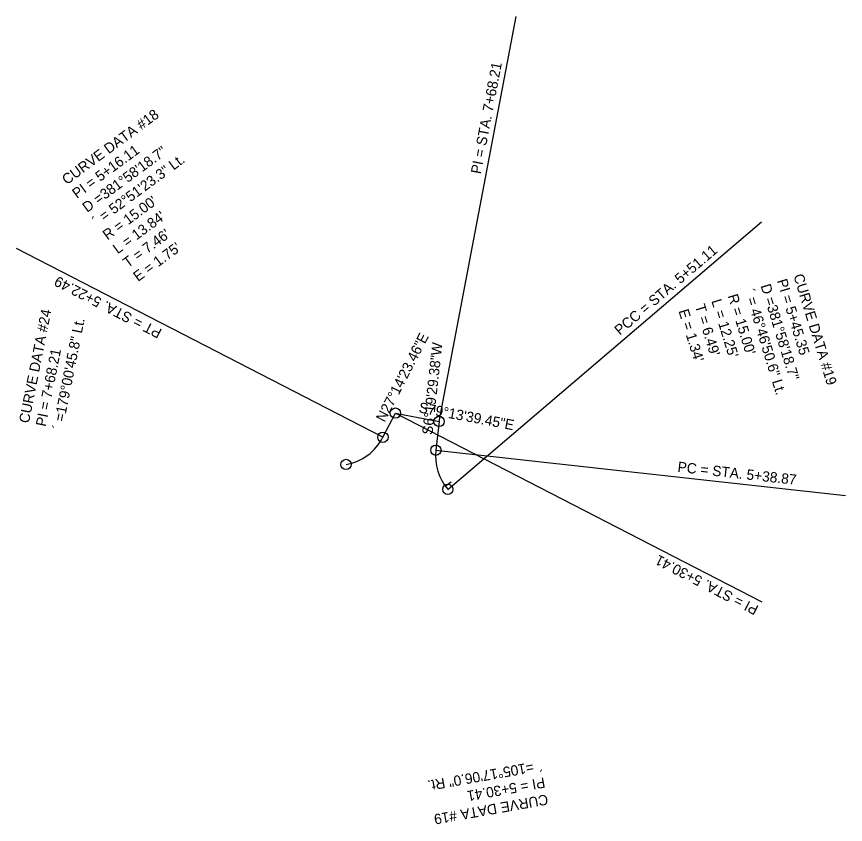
# Model space of a CAD drawing. Extents: x 1158784 to 1165006, y 610007 to 611539.
# Drawn here: x 1162069.8 to 1162311.2, y 610604.7 to 610839.9 of the extents above; entities that cross this region are included whole.
import ezdxf

# ---------------------------------------------------------------- set-up
doc = ezdxf.new("R2010")
doc.units = 0
for name, color, linetype in [('D_Roadway_Centerline', 7, 'Continuous'), ('D_Roadway_Centerline_Bearings', 7, 'Continuous'), ('D_Roadway_Centerline_CurveData', 7, 'Continuous'), ('D_Roadway_Centerline_Flags', 7, 'Continuous'), ('D_Roadway_Centerline_Text', 7, 'Continuous')]:
    doc.layers.add(name, color=color, linetype=linetype)

msp = doc.modelspace()

# ---------------------------------------------------------------- linework, layer by layer
at = {"layer": 'D_Roadway_Centerline'}
for p, q in [((1162176.52, 610717.41), (1162180.14, 610724.45)), ((1162180.14, 610724.45), (1162192.85, 610722.03)), ((1162192.85, 610722.05), (1162191.92, 610713.65))]:
    msp.add_line(p, q, dxfattribs=at)
for centre, start, end in [((1162163.18, 610724.28), 279.9037, 332.7602), ((1162206.83, 610712), 173.6752, 220.4559)]:
    msp.add_arc(centre, 15, start, end, dxfattribs=at)
at = {"layer": 'D_Roadway_Centerline_Flags'}
for points in [[(1162192.85, 610722.03), (1162215.28, 610839.92)], [(1162195.41, 610702.26), (1162286.72, 610780.13)], [(1162176.52, 610717.41), (1162069.83, 610772.34)], [(1162180.14, 610724.45), (1162286.83, 610669.52)], [(1162191.92, 610713.65), (1162311.19, 610700.43)]]:
    msp.add_lwpolyline(points, dxfattribs=at)
for centre in [(1162180.14, 610724.45), (1162180.14, 610724.45), (1162192.85, 610722.05), (1162192.85, 610722.03), (1162176.52, 610717.41), (1162191.92, 610713.65), (1162165.76, 610709.5), (1162195.41, 610702.26)]:
    msp.add_circle(centre, 1.5, dxfattribs=at)
at = {"layer": 'D_Roadway_Centerline_Text'}
msp.add_lwpolyline([(1162196.34, 610704.32), (1162194.72, 610703.14)], dxfattribs=at)

# ---------------------------------------------------------------- texts
at = {"layer": 'D_Roadway_Centerline_Bearings'}
for s, rotation, p in [('N27%%d14\'23.46"E', 62.7602, (1162176.99, 610721.62)), ('S6%%d19\'29.38"W', 83.6752, (1162190.89, 610718.02)), ('S79%%d13\'39.45"E', 349.2276, (1162186.77, 610724.71))]:
    msp.add_text(s, height=3, rotation=rotation, dxfattribs=at).set_placement(p)
at = {"layer": 'D_Roadway_Centerline_CurveData'}
for s, rotation, p in [('CURVE DATA #18', 36.3319, (1162084.45, 610790.82)), ('PI = 5+16.11', 36.3319, (1162087.41, 610786.79)), ('D =381%%d58\'18.7"', 36.3319, (1162090.38, 610782.76)), ('´ = 52%%d51\'23.3" Lt.', 36.3319, (1162093.34, 610778.74)), ("R = 15.00'", 36.3319, (1162096.3, 610774.71)), ("L = 13.84'", 36.3319, (1162099.26, 610770.68)), ("T = 7.46'", 36.3319, (1162102.23, 610766.65)), ("E = 1.75'", 36.3319, (1162105.19, 610762.62)), ('CURVE DATA #19', 287.0655, (1162296.01, 610764.48)), ('D =381%%d58\'18.7"', 287.0655, (1162286.45, 610761.54)), ('PI = 5+45.35', 287.0655, (1162291.23, 610763.01)), ("R = 15.00'", 287.0655, (1162276.89, 610758.61)), ('´ = 46%%d46\'50.6" Lt.', 287.0655, (1162281.67, 610760.08)), ("L = 12.25'", 287.0655, (1162272.11, 610757.14)), ('CURVE DATA #24', 78.734, (1162073.41, 610721.35)), ("E = 1.34'", 287.0655, (1162262.55, 610754.21)), ("T = 6.49'", 287.0655, (1162267.33, 610755.67)), ('´ =179%%d00\'45.8" Lt.', 78.734, (1162083.22, 610719.4)), ('PI = 7+68.21', 78.734, (1162078.32, 610720.38)), ('´ =105%%d17\'06.0" Rt.', 190.1176, (1162222.56, 610623.33)), ('PI = 5+30.41', 190.1176, (1162223.44, 610618.41)), ('CURVE DATA #19', 190.1176, (1162224.32, 610613.49))]:
    msp.add_text(s, height=3, rotation=rotation, dxfattribs=at).set_placement(p)
at = {"layer": 'D_Roadway_Centerline_Flags'}
for s, rotation, p in [('PI = STA. 7+68.21', 79.2276, (1162205, 610793.93)), ('PCC = STA. 5+51.11', 40.4559, (1162245.51, 610746.96)), ('PT = STA. 5+22.49', 152.7602, (1162112.38, 610748.74)), ('PC = STA. 5+38.87', 353.6752, (1162262.19, 610707.37)), ('PI = STA. 5+30.41', 152.7602, (1162286.15, 610668.19))]:
    msp.add_text(s, height=3, rotation=rotation, dxfattribs=at).set_placement(p)

doc.saveas('drawing.dxf')
